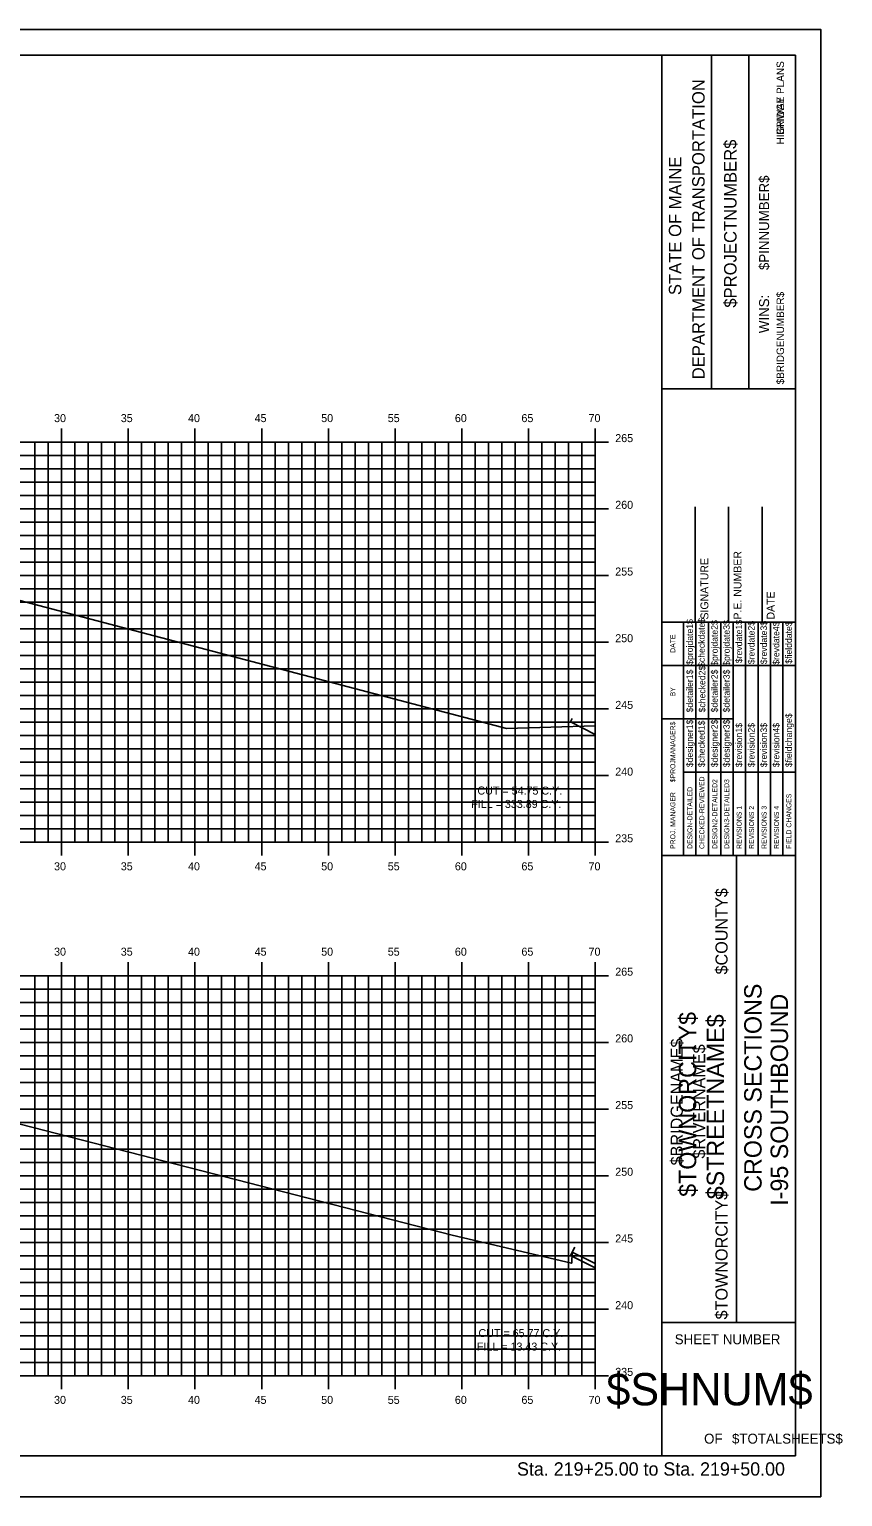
# Model space of a CAD drawing. Extents: x -22 to 1480, y -1511 to 8.
# Drawn here: x 310.3 to 371.2, y -184.5 to -74.5 of the extents above; entities that cross this region are included whole.
import ezdxf

# ---------------------------------------------------------------- set-up
doc = ezdxf.new("R2010")
doc.units = 0
for name, color, linetype in [('ANNOTATION', 7, 'Continuous'), ('BORDER', 7, 'Continuous'), ('BRIDGE_TITLE', 7, 'Continuous'), ('D_Utilities_UG_Water_Shutoff', 7, 'Continuous'), ('H_V ANNOTATION', 7, 'Continuous'), ('HIGHWAY_TITLE', 7, 'Continuous'), ('MAJOR', 7, 'Continuous'), ('MINOR', 7, 'Continuous'), ('PLOT BOUNDARY', 7, 'Continuous'), ('S_Roadway_Centerline', 7, 'Continuous')]:
    doc.layers.add(name, color=color, linetype=linetype)

msp = doc.modelspace()

# ---------------------------------------------------------------- linework, layer by layer
at = {"layer": 'BORDER'}
for p, q in [((367.7, -76.47), (207.7, -76.47)), ((357.7, -181.46), (357.7, -76.46)), ((361.42, -101.47), (361.42, -76.47)), ((364.22, -101.47), (364.22, -76.47)), ((367.7, -181.46), (367.7, -76.46)), ((357.7, -101.47), (367.7, -101.47)), ((360.2, -118.96), (360.2, -110.32)), ((362.7, -118.96), (362.7, -110.32)), ((365.2, -118.96), (365.2, -110.32)), ((357.7, -118.96), (367.7, -118.96)), ((357.7, -136.46), (367.7, -136.46)), ((363.29, -171.46), (363.29, -136.46)), ((357.7, -171.46), (367.7, -171.46)), ((207.7, -181.47), (367.7, -181.47))]:
    msp.add_line(p, q, dxfattribs=at)
for points in [[(359.31, -122.21), (359.31, -118.96)], [(359.31, -136.46), (359.31, -119.67)], [(360.24, -136.46), (360.24, -118.96)], [(361.18, -118.96), (361.18, -136.46)], [(362.11, -136.46), (362.11, -118.96)], [(363.04, -136.46), (363.04, -118.96)], [(363.97, -136.46), (363.97, -118.96)], [(364.9, -136.46), (364.9, -118.96)], [(365.83, -136.46), (365.83, -118.96)], [(366.77, -136.46), (366.77, -118.96)], [(357.7, -122.21), (367.7, -122.21)], [(357.7, -126.21), (359.31, -126.21)], [(359.31, -126.21), (363.04, -126.21)], [(359.31, -130.21), (367.7, -130.21)]]:
    msp.add_lwpolyline(points, dxfattribs=at)
at = {"layer": 'D_Utilities_UG_Water_Shutoff'}
for points in [[(350.98, -126.19), (350.85, -126.44), (352.7, -127.38)], [(351.17, -165.81), (350.85, -166.44), (352.7, -167.38)]]:
    msp.add_lwpolyline(points, dxfattribs=at)
at = {"layer": 'MAJOR'}
for p, q in [((312.7, -104.46), (312.7, -105.47)), ((317.7, -104.46), (317.7, -105.47)), ((322.7, -104.46), (322.7, -105.47)), ((327.7, -104.46), (327.7, -105.47)), ((332.7, -104.46), (332.7, -105.47)), ((337.7, -104.46), (337.7, -105.47)), ((342.7, -104.46), (342.7, -105.47)), ((347.7, -104.46), (347.7, -105.47)), ((352.7, -104.46), (352.7, -105.47)), ((212.7, -105.47), (352.7, -105.47)), ((212.7, -105.47), (352.7, -105.47)), ((312.7, -135.47), (312.7, -105.47)), ((317.7, -135.47), (317.7, -105.47)), ((322.7, -135.47), (322.7, -105.47)), ((327.7, -135.47), (327.7, -105.47)), ((332.7, -135.47), (332.7, -105.47)), ((337.7, -135.47), (337.7, -105.47)), ((342.7, -135.47), (342.7, -105.47)), ((347.7, -135.47), (347.7, -105.47)), ((353.7, -105.47), (351.69, -105.47)), ((352.7, -135.47), (352.7, -105.47)), ((352.7, -135.47), (352.7, -105.47)), ((212.7, -110.47), (352.7, -110.47)), ((353.7, -110.47), (351.69, -110.47)), ((212.7, -115.47), (352.7, -115.47)), ((353.7, -115.47), (351.69, -115.47)), ((212.7, -120.47), (352.7, -120.47)), ((353.7, -120.47), (351.69, -120.47)), ((212.7, -125.47), (352.7, -125.47)), ((353.7, -125.47), (351.69, -125.47)), ((212.7, -130.47), (352.7, -130.47)), ((353.7, -130.47), (351.69, -130.47)), ((212.7, -135.47), (352.7, -135.47)), ((212.7, -135.47), (352.7, -135.47)), ((312.7, -136.47), (312.7, -135.47)), ((317.7, -136.47), (317.7, -135.47)), ((322.7, -136.47), (322.7, -135.47)), ((327.7, -136.47), (327.7, -135.47)), ((332.7, -136.47), (332.7, -135.47)), ((337.7, -136.47), (337.7, -135.47)), ((342.7, -136.47), (342.7, -135.47)), ((347.7, -136.47), (347.7, -135.47)), ((353.7, -135.47), (351.69, -135.47)), ((352.7, -136.47), (352.7, -135.47)), ((312.7, -144.46), (312.7, -145.47)), ((317.7, -144.46), (317.7, -145.47)), ((322.7, -144.46), (322.7, -145.47)), ((327.7, -144.46), (327.7, -145.47)), ((332.7, -144.46), (332.7, -145.47)), ((337.7, -144.46), (337.7, -145.47)), ((342.7, -144.46), (342.7, -145.47)), ((347.7, -144.46), (347.7, -145.47)), ((352.7, -144.46), (352.7, -145.47)), ((212.7, -145.47), (352.7, -145.47)), ((212.7, -145.47), (352.7, -145.47)), ((312.7, -175.47), (312.7, -145.47)), ((317.7, -175.47), (317.7, -145.47)), ((322.7, -175.47), (322.7, -145.47)), ((327.7, -175.47), (327.7, -145.47)), ((332.7, -175.47), (332.7, -145.47)), ((337.7, -175.47), (337.7, -145.47)), ((342.7, -175.47), (342.7, -145.47)), ((347.7, -175.47), (347.7, -145.47)), ((353.7, -145.47), (351.69, -145.47)), ((352.7, -175.47), (352.7, -145.47)), ((352.7, -175.47), (352.7, -145.47)), ((212.7, -150.47), (352.7, -150.47)), ((353.7, -150.47), (351.69, -150.47)), ((212.7, -155.47), (352.7, -155.47)), ((353.7, -155.47), (351.69, -155.47)), ((212.7, -160.47), (352.7, -160.47)), ((353.7, -160.47), (351.69, -160.47)), ((212.7, -165.47), (352.7, -165.47)), ((353.7, -165.47), (351.69, -165.47)), ((212.7, -170.47), (352.7, -170.47)), ((353.7, -170.47), (351.69, -170.47)), ((212.7, -175.47), (352.7, -175.47)), ((212.7, -175.47), (352.7, -175.47)), ((312.7, -176.47), (312.7, -175.47)), ((317.7, -176.47), (317.7, -175.47)), ((322.7, -176.47), (322.7, -175.47)), ((327.7, -176.47), (327.7, -175.47)), ((332.7, -176.47), (332.7, -175.47)), ((337.7, -176.47), (337.7, -175.47)), ((342.7, -176.47), (342.7, -175.47)), ((347.7, -176.47), (347.7, -175.47)), ((353.7, -175.47), (351.69, -175.47)), ((352.7, -176.47), (352.7, -175.47))]:
    msp.add_line(p, q, dxfattribs=at)
at = {"layer": 'MINOR'}
for p, q in [((310.7, -135.47), (310.7, -105.47)), ((311.7, -135.47), (311.7, -105.47)), ((313.7, -135.47), (313.7, -105.47)), ((314.7, -135.47), (314.7, -105.47)), ((315.7, -135.47), (315.7, -105.47)), ((316.7, -135.47), (316.7, -105.47)), ((318.7, -135.47), (318.7, -105.47)), ((319.7, -135.47), (319.7, -105.47)), ((320.7, -135.47), (320.7, -105.47)), ((321.7, -135.47), (321.7, -105.47)), ((323.7, -135.47), (323.7, -105.47)), ((324.7, -135.47), (324.7, -105.47)), ((325.7, -135.47), (325.7, -105.47)), ((326.7, -135.47), (326.7, -105.47)), ((328.7, -135.47), (328.7, -105.47)), ((329.7, -135.47), (329.7, -105.47)), ((330.7, -135.47), (330.7, -105.47)), ((331.7, -135.47), (331.7, -105.47)), ((333.7, -135.47), (333.7, -105.47)), ((334.7, -135.47), (334.7, -105.47)), ((335.7, -135.47), (335.7, -105.47)), ((336.7, -135.47), (336.7, -105.47)), ((338.7, -135.47), (338.7, -105.47)), ((339.7, -135.47), (339.7, -105.47)), ((340.7, -135.47), (340.7, -105.47)), ((341.7, -135.47), (341.7, -105.47)), ((343.7, -135.47), (343.7, -105.47)), ((344.7, -135.47), (344.7, -105.47)), ((345.7, -135.47), (345.7, -105.47)), ((346.7, -135.47), (346.7, -105.47)), ((348.7, -135.47), (348.7, -105.47)), ((349.7, -135.47), (349.7, -105.47)), ((350.7, -135.47), (350.7, -105.47)), ((351.7, -135.47), (351.7, -105.47)), ((212.7, -106.47), (352.7, -106.47)), ((352.7, -106.47), (351.69, -106.47)), ((212.7, -107.47), (352.7, -107.47)), ((352.7, -107.47), (351.69, -107.47)), ((212.7, -108.47), (352.7, -108.47)), ((352.7, -108.47), (351.69, -108.47)), ((212.7, -109.47), (352.7, -109.47)), ((352.7, -109.47), (351.69, -109.47)), ((212.7, -111.47), (352.7, -111.47)), ((352.7, -111.47), (351.69, -111.47)), ((212.7, -112.47), (352.7, -112.47)), ((352.7, -112.47), (351.69, -112.47)), ((212.7, -113.47), (352.7, -113.47)), ((352.7, -113.47), (351.69, -113.47)), ((212.7, -114.47), (352.7, -114.47)), ((352.7, -114.47), (351.69, -114.47)), ((212.7, -116.47), (352.7, -116.47)), ((352.7, -116.47), (351.69, -116.47)), ((212.7, -117.47), (352.7, -117.47)), ((352.7, -117.47), (351.69, -117.47)), ((212.7, -118.47), (352.7, -118.47)), ((352.7, -118.47), (351.69, -118.47)), ((212.7, -119.47), (352.7, -119.47)), ((352.7, -119.47), (351.69, -119.47)), ((212.7, -121.47), (352.7, -121.47)), ((352.7, -121.47), (351.69, -121.47)), ((212.7, -122.47), (352.7, -122.47)), ((352.7, -122.47), (351.69, -122.47)), ((212.7, -123.47), (352.7, -123.47)), ((352.7, -123.47), (351.69, -123.47)), ((212.7, -124.47), (352.7, -124.47)), ((352.7, -124.47), (351.69, -124.47)), ((212.7, -126.47), (352.7, -126.47)), ((352.7, -126.47), (351.69, -126.47)), ((212.7, -127.47), (352.7, -127.47)), ((352.7, -127.47), (351.69, -127.47)), ((212.7, -128.47), (352.7, -128.47)), ((352.7, -128.47), (351.69, -128.47)), ((212.7, -129.47), (352.7, -129.47)), ((352.7, -129.47), (351.69, -129.47)), ((212.7, -131.47), (352.7, -131.47)), ((352.7, -131.47), (351.69, -131.47)), ((212.7, -132.47), (352.7, -132.47)), ((352.7, -132.47), (351.69, -132.47)), ((212.7, -133.47), (352.7, -133.47)), ((352.7, -133.47), (351.69, -133.47)), ((212.7, -134.47), (352.7, -134.47)), ((352.7, -134.47), (351.69, -134.47)), ((310.7, -175.47), (310.7, -145.47)), ((311.7, -175.47), (311.7, -145.47)), ((313.7, -175.47), (313.7, -145.47)), ((314.7, -175.47), (314.7, -145.47)), ((315.7, -175.47), (315.7, -145.47)), ((316.7, -175.47), (316.7, -145.47)), ((318.7, -175.47), (318.7, -145.47)), ((319.7, -175.47), (319.7, -145.47)), ((320.7, -175.47), (320.7, -145.47)), ((321.7, -175.47), (321.7, -145.47)), ((323.7, -175.47), (323.7, -145.47)), ((324.7, -175.47), (324.7, -145.47)), ((325.7, -175.47), (325.7, -145.47)), ((326.7, -175.47), (326.7, -145.47)), ((328.7, -175.47), (328.7, -145.47)), ((329.7, -175.47), (329.7, -145.47)), ((330.7, -175.47), (330.7, -145.47)), ((331.7, -175.47), (331.7, -145.47)), ((333.7, -175.47), (333.7, -145.47)), ((334.7, -175.47), (334.7, -145.47)), ((335.7, -175.47), (335.7, -145.47)), ((336.7, -175.47), (336.7, -145.47)), ((338.7, -175.47), (338.7, -145.47)), ((339.7, -175.47), (339.7, -145.47)), ((340.7, -175.47), (340.7, -145.47)), ((341.7, -175.47), (341.7, -145.47)), ((343.7, -175.47), (343.7, -145.47)), ((344.7, -175.47), (344.7, -145.47)), ((345.7, -175.47), (345.7, -145.47)), ((346.7, -175.47), (346.7, -145.47)), ((348.7, -175.47), (348.7, -145.47)), ((349.7, -175.47), (349.7, -145.47)), ((350.7, -175.47), (350.7, -145.47)), ((351.7, -175.47), (351.7, -145.47)), ((212.7, -146.47), (352.7, -146.47)), ((352.7, -146.47), (351.69, -146.47)), ((212.7, -147.47), (352.7, -147.47)), ((212.7, -148.47), (352.7, -148.47)), ((352.7, -147.47), (351.69, -147.47)), ((352.7, -148.47), (351.69, -148.47)), ((212.7, -149.47), (352.7, -149.47)), ((352.7, -149.47), (351.69, -149.47)), ((212.7, -151.47), (352.7, -151.47)), ((352.7, -151.47), (351.69, -151.47)), ((212.7, -152.47), (352.7, -152.47)), ((352.7, -152.47), (351.69, -152.47)), ((212.7, -153.47), (352.7, -153.47)), ((352.7, -153.47), (351.69, -153.47)), ((212.7, -154.47), (352.7, -154.47)), ((352.7, -154.47), (351.69, -154.47)), ((212.7, -156.47), (352.7, -156.47)), ((352.7, -156.47), (351.69, -156.47)), ((212.7, -157.47), (352.7, -157.47)), ((352.7, -157.47), (351.69, -157.47)), ((212.7, -158.47), (352.7, -158.47)), ((212.7, -159.47), (352.7, -159.47)), ((352.7, -158.47), (351.69, -158.47)), ((352.7, -159.47), (351.69, -159.47)), ((212.7, -161.47), (352.7, -161.47)), ((352.7, -161.47), (351.69, -161.47)), ((212.7, -162.47), (352.7, -162.47)), ((352.7, -162.47), (351.69, -162.47)), ((212.7, -163.47), (352.7, -163.47)), ((352.7, -163.47), (351.69, -163.47)), ((212.7, -164.47), (352.7, -164.47)), ((352.7, -164.47), (351.69, -164.47)), ((212.7, -166.47), (352.7, -166.47)), ((352.7, -166.47), (351.69, -166.47)), ((212.7, -167.47), (352.7, -167.47)), ((352.7, -167.47), (351.69, -167.47)), ((212.7, -168.47), (352.7, -168.47)), ((352.7, -168.47), (351.69, -168.47)), ((212.7, -169.47), (352.7, -169.47)), ((352.7, -169.47), (351.69, -169.47)), ((212.7, -171.47), (352.7, -171.47)), ((352.7, -171.47), (351.69, -171.47)), ((212.7, -172.47), (352.7, -172.47)), ((352.7, -172.47), (351.69, -172.47)), ((212.7, -173.47), (352.7, -173.47)), ((352.7, -173.47), (351.69, -173.47)), ((212.7, -174.47), (352.7, -174.47)), ((352.7, -174.47), (351.69, -174.47))]:
    msp.add_line(p, q, dxfattribs=at)
at = {"layer": 'PLOT BOUNDARY'}
msp.add_lwpolyline([(199.6, -184.53), (369.6, -184.53), (369.6, -74.53), (199.6, -74.53)], close=True, dxfattribs=at)
at = {"layer": 'S_Roadway_Centerline'}
for points in [[(307.07, -116.69), (343.87, -126.36), (346.06, -126.95), (352.7, -126.73)], [(305.11, -155.44), (341.98, -164.91), (350.93, -167.02), (350.94, -167.02), (350.98, -166.19), (352.7, -167.05)]]:
    msp.add_lwpolyline(points, dxfattribs=at)

# ---------------------------------------------------------------- texts
at = {"layer": 'ANNOTATION'}
for s, p in [('CUT = 54.75 C.Y.', (343.87, -131.89)), ('FILL = 333.89 C.Y.', (343.41, -132.89)), ('CUT = 65.77 C.Y.', (343.95, -172.56)), ('FILL = 13.43 C.Y.', (343.83, -173.57))]:
    msp.add_text(s, height=0.6, rotation=359.9241, dxfattribs=at).set_placement(p)
at = {"layer": 'BORDER'}
for s, height, rotation, p in [('DEPARTMENT OF TRANSPORTATION', 0.9318, 90, (360.9, -100.76)), ('$PROJECTNUMBER$', 0.9318, 90, (363.29, -95.39)), ('STATE OF MAINE', 0.9318, 90, (359.15, -94.45)), ('$PINNUMBER$', 0.7453, 90, (365.73, -92.57)), ('WINS:', 0.745, 90, (365.73, -97.3)), ('SIGNATURE', 0.591, 90, (361.18, -118.77)), ('P.E. NUMBER', 0.5906, 90, (363.66, -118.77)), ('DATE', 0.591, 90, (366.14, -118.77)), ('$projdate1$', 0.4845, 90, (360.02, -122.16)), ('$checkdate$', 0.4845, 90, (360.91, -122.32)), ('$projdate2$', 0.4845, 90, (361.88, -122.24)), ('$projdate3$', 0.4845, 90, (362.78, -122.24)), ('$revdate1$', 0.485, 90, (363.71, -122.04)), ('$revdate2$', 0.485, 90, (364.64, -122.12)), ('$revdate3$', 0.485, 90, (365.57, -122.12)), ('$revdate4$', 0.485, 90, (366.5, -122.16)), ('$fielddate$', 0.4845, 90, (367.44, -122.08)), ('DATE', 0.371, 90, (358.7, -121.26)), ('$detailer1$', 0.4845, 90, (360.02, -125.73)), ('$checked2$', 0.485, 90, (360.95, -125.73)), ('$detailer2$', 0.4845, 90, (361.88, -125.73)), ('$detailer3$', 0.4845, 90, (362.78, -125.73)), ('BY', 0.371, 90, (358.7, -124.53)), ('$designer1$', 0.4845, 90, (360.02, -129.84)), ('$checked1$', 0.485, 90, (360.91, -129.84)), ('$designer2$', 0.4845, 90, (361.88, -129.84)), ('$designer3$', 0.4845, 90, (362.78, -129.84)), ('$fieldchange$', 0.4845, 90, (367.44, -129.84)), ('$PROJMANAGER$', 0.3727, 90, (358.7, -130.97)), ('$revision1$', 0.4845, 90, (363.71, -129.84)), ('$revision2$', 0.4845, 90, (364.64, -129.84)), ('$revision3$', 0.4845, 90, (365.57, -129.84)), ('$revision4$', 0.4845, 90, (366.5, -129.84)), ('CHECKED-REVIEWED', 0.3727, 90, (360.88, -135.97)), ('PROJ. MANAGER', 0.3727, 90, (358.7, -135.97)), ('DESIGN-DETAILED', 0.3727, 90, (359.98, -135.97)), ('DESIGN2-DETAILED2', 0.3727, 90, (361.85, -135.97)), ('DESIGN3-DETAILED3', 0.3727, 90, (362.74, -135.97)), ('FIELD CHANGES', 0.3727, 90, (367.4, -135.97)), ('REVISIONS 1', 0.3727, 90, (363.67, -135.97)), ('REVISIONS 2', 0.3727, 90, (364.6, -135.97)), ('REVISIONS 3', 0.3727, 90, (365.54, -135.97)), ('REVISIONS 4', 0.3727, 90, (366.47, -135.97)), ('CROSS SECTIONS', 1.3043, 90, (365.17, -161.67)), ('I-95 SOUTHBOUND', 1.3043, 90, (367.15, -162.72)), ('SHEET NUMBER', 0.7453, 360, (358.66, -173.1)), ('$SHNUM$', 2.419, 360, (353.53, -177.68)), ('OF', 0.745, 360, (360.86, -180.55)), ('$TOTALSHEETS$', 0.7453, 360, (362.95, -180.55))]:
    msp.add_text(s, height=height, rotation=rotation, dxfattribs=at).set_placement(p)
at = {"layer": 'BRIDGE_TITLE'}
for s, height, p in [('BRIDGE PLANS', 0.559, (366.85, -82.44)), ('$BRIDGENUMBER$', 0.559, (366.85, -101.14)), ('$COUNTY$', 0.907, (362.62, -145.38)), ('$BRIDGENAME$', 0.9072, (359.26, -159.69)), ('$RIVERNAME$', 0.9072, (360.94, -159.18)), ('$TOWNORCITY$', 0.9072, (362.62, -171.24))]:
    msp.add_text(s, height=height, rotation=90, dxfattribs=at).set_placement(p)
at = {"layer": 'H_V ANNOTATION'}
for s, height, p in [('30', 0.6, (312.14, -103.97)), ('35', 0.6, (317.14, -103.97)), ('40', 0.6, (322.18, -103.97)), ('45', 0.6, (327.17, -103.97)), ('50', 0.6, (332.16, -103.97)), ('55', 0.6, (337.15, -103.97)), ('60', 0.6, (342.18, -103.97)), ('65', 0.6, (347.17, -103.97)), ('70', 0.6, (352.2, -103.97)), ('265', 0.6, (354.2, -105.47)), ('260', 0.6, (354.2, -110.47)), ('255', 0.6, (354.2, -115.47)), ('250', 0.6, (354.2, -120.47)), ('245', 0.6, (354.2, -125.47)), ('240', 0.6, (354.2, -130.47)), ('235', 0.6, (354.2, -135.47)), ('30', 0.6, (312.14, -137.57)), ('35', 0.6, (317.14, -137.57)), ('40', 0.6, (322.18, -137.57)), ('45', 0.6, (327.17, -137.57)), ('50', 0.6, (332.16, -137.57)), ('55', 0.6, (337.15, -137.57)), ('60', 0.6, (342.18, -137.57)), ('65', 0.6, (347.17, -137.57)), ('70', 0.6, (352.2, -137.57)), ('30', 0.6, (312.14, -143.97)), ('35', 0.6, (317.14, -143.97)), ('40', 0.6, (322.18, -143.97)), ('45', 0.6, (327.17, -143.97)), ('50', 0.6, (332.16, -143.97)), ('55', 0.6, (337.15, -143.97)), ('60', 0.6, (342.18, -143.97)), ('65', 0.6, (347.17, -143.97)), ('70', 0.6, (352.2, -143.97)), ('265', 0.6, (354.2, -145.47)), ('260', 0.6, (354.2, -150.47)), ('255', 0.6, (354.2, -155.47)), ('250', 0.6, (354.2, -160.47)), ('245', 0.6, (354.2, -165.47)), ('240', 0.6, (354.2, -170.47)), ('235', 0.6, (354.2, -175.47)), ('30', 0.6, (312.14, -177.57)), ('35', 0.6, (317.14, -177.57)), ('40', 0.6, (322.18, -177.57)), ('45', 0.6, (327.17, -177.57)), ('50', 0.6, (332.16, -177.57)), ('55', 0.6, (337.15, -177.57)), ('60', 0.6, (342.18, -177.57)), ('65', 0.6, (347.17, -177.57)), ('70', 0.6, (352.2, -177.57)), ('Sta. 219+25.00 to Sta. 219+50.00', 1.0002, (346.84, -182.95))]:
    msp.add_text(s, height=height, dxfattribs=at).set_placement(p)
at = {"layer": 'HIGHWAY_TITLE'}
for s, height, p in [('HIGHWAY PLANS', 0.559, (366.85, -83.15)), ('$TOWNORCITY$', 1.3043, (360.27, -162.05)), ('$STREETNAME$', 1.3043, (362.36, -162.23))]:
    msp.add_text(s, height=height, rotation=90, dxfattribs=at).set_placement(p)

doc.saveas('drawing.dxf')
